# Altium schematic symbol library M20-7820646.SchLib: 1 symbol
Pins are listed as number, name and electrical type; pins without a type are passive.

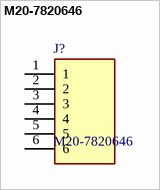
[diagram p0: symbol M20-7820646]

## M20-7820646
designator J?
M20: 6 Pos Receptacle SIL Straight 3mm THT Connector 8.5mm high Tin; Manufacturer_Name: Harwin
footprint HDRV6W70P0X254_1X6_1564X250X850P
pins: 1, 2, 3, 4, 5, 6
